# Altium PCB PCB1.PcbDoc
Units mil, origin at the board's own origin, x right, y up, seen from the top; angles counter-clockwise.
Board outline 2756 x 2756 mil, 4 copper layers (Top Layer, Internal Plane 1, Internal Plane 2, Bottom Layer), stack 18.2 mil thick; 17 components, 15 nets, 62 pads, 0 vias.
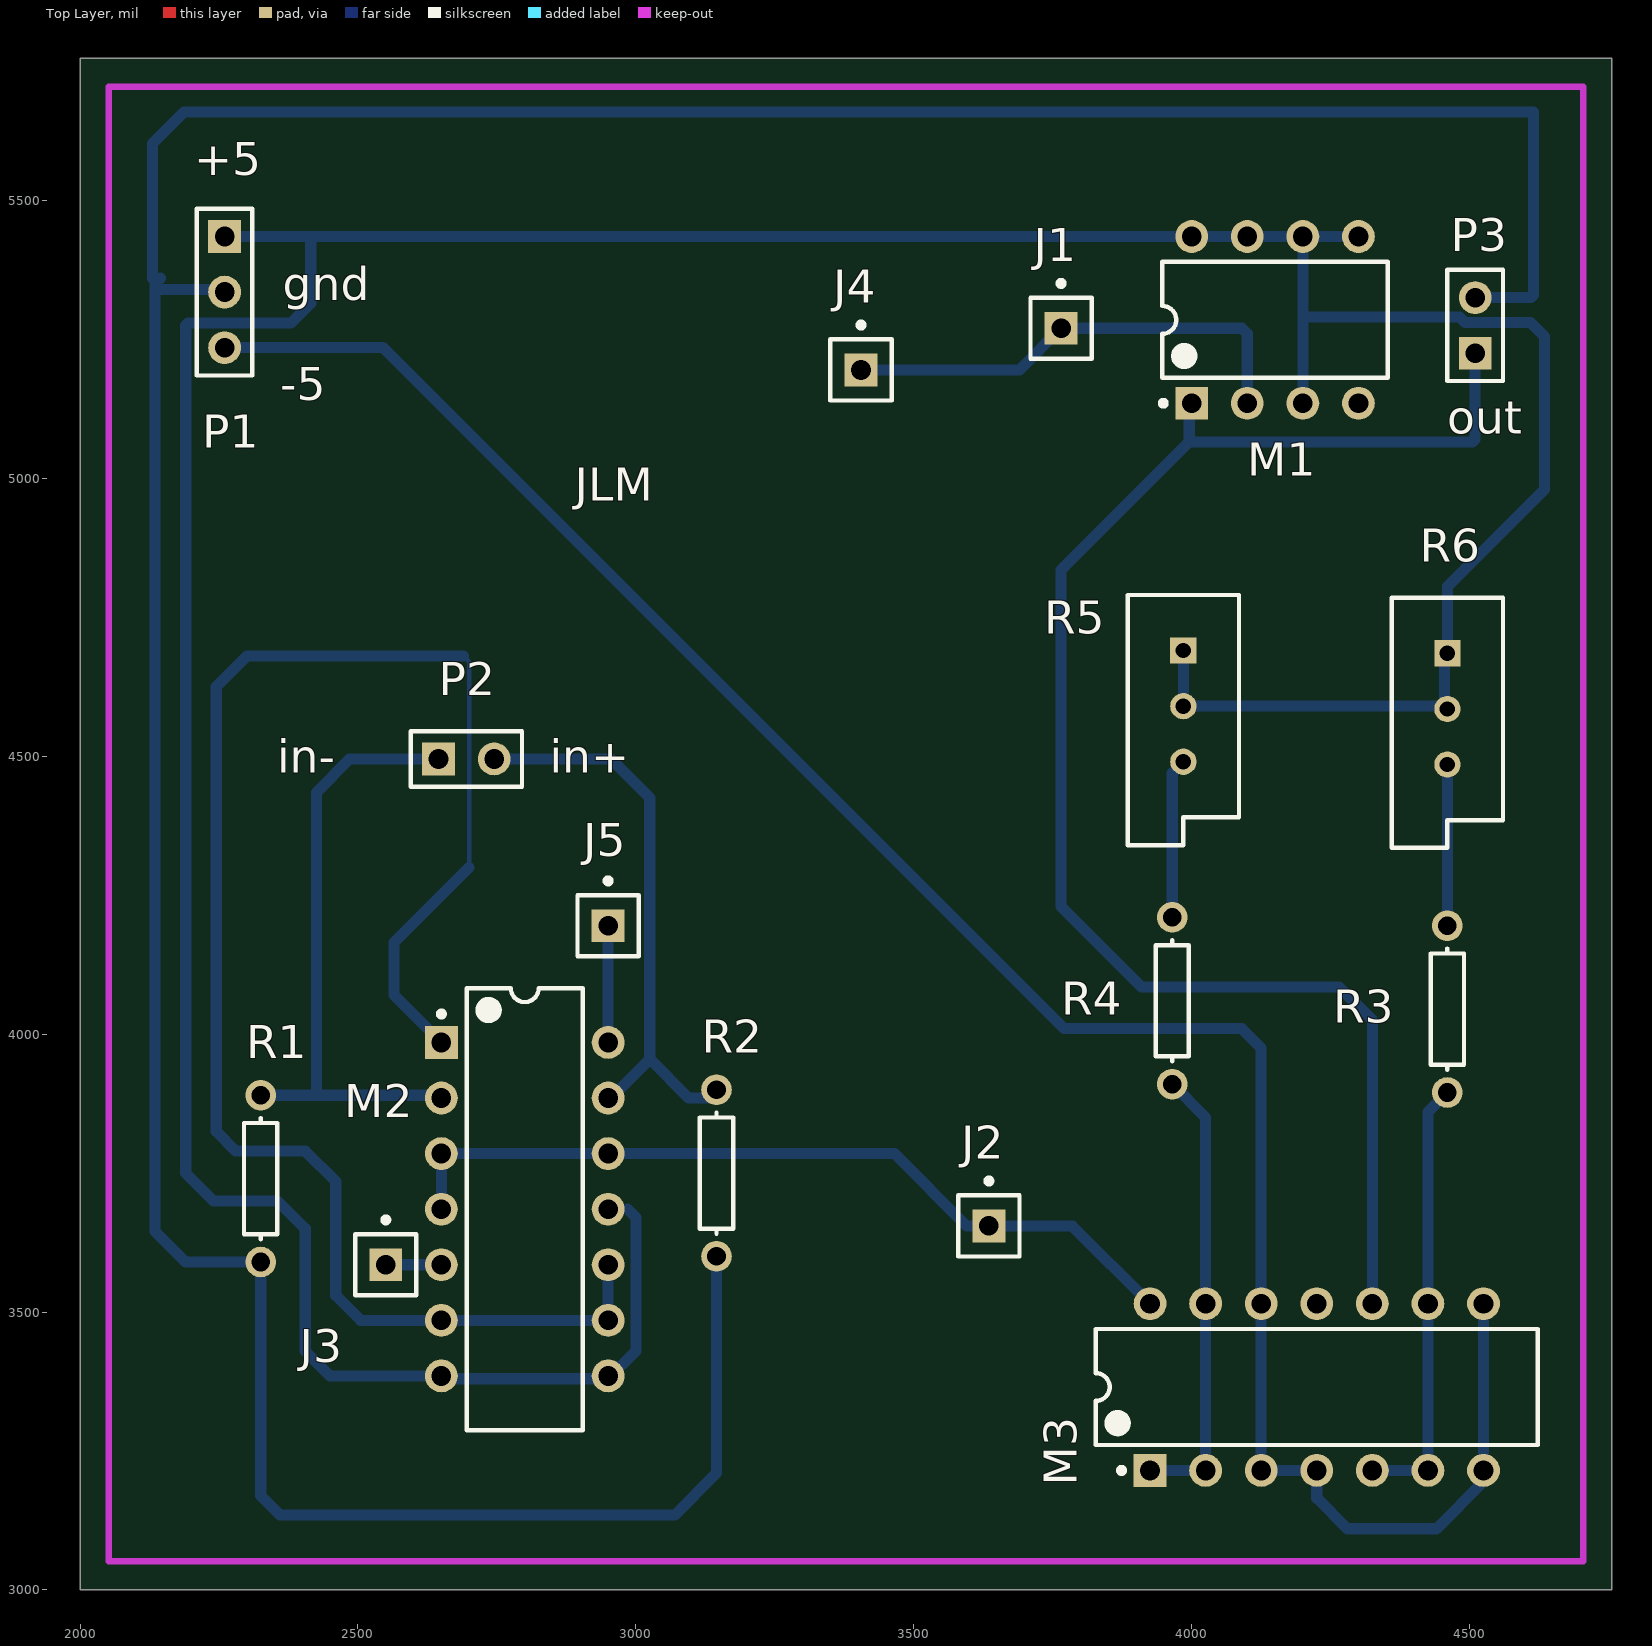
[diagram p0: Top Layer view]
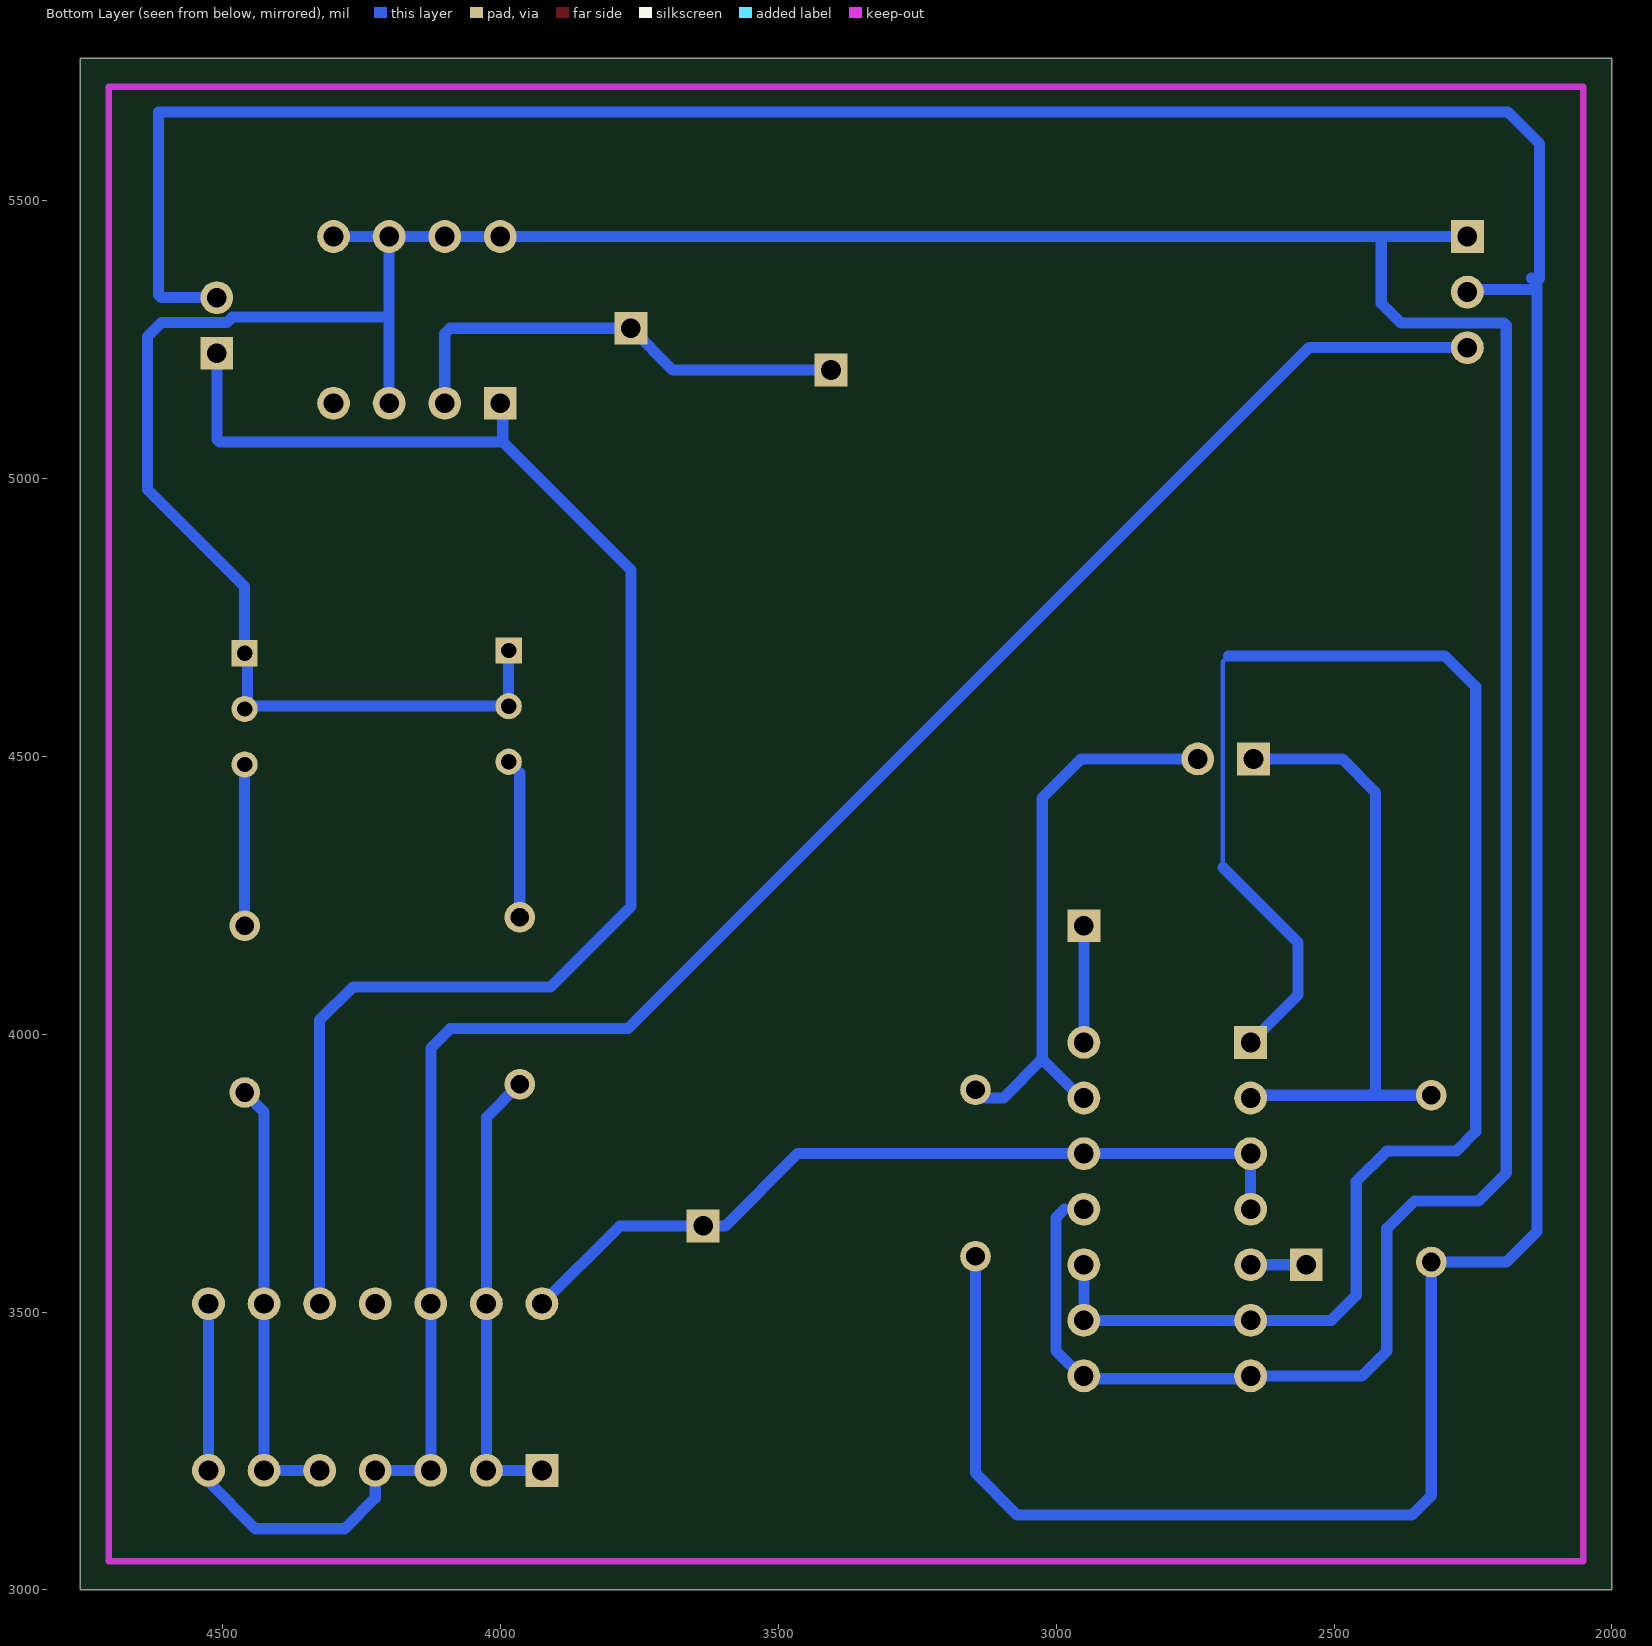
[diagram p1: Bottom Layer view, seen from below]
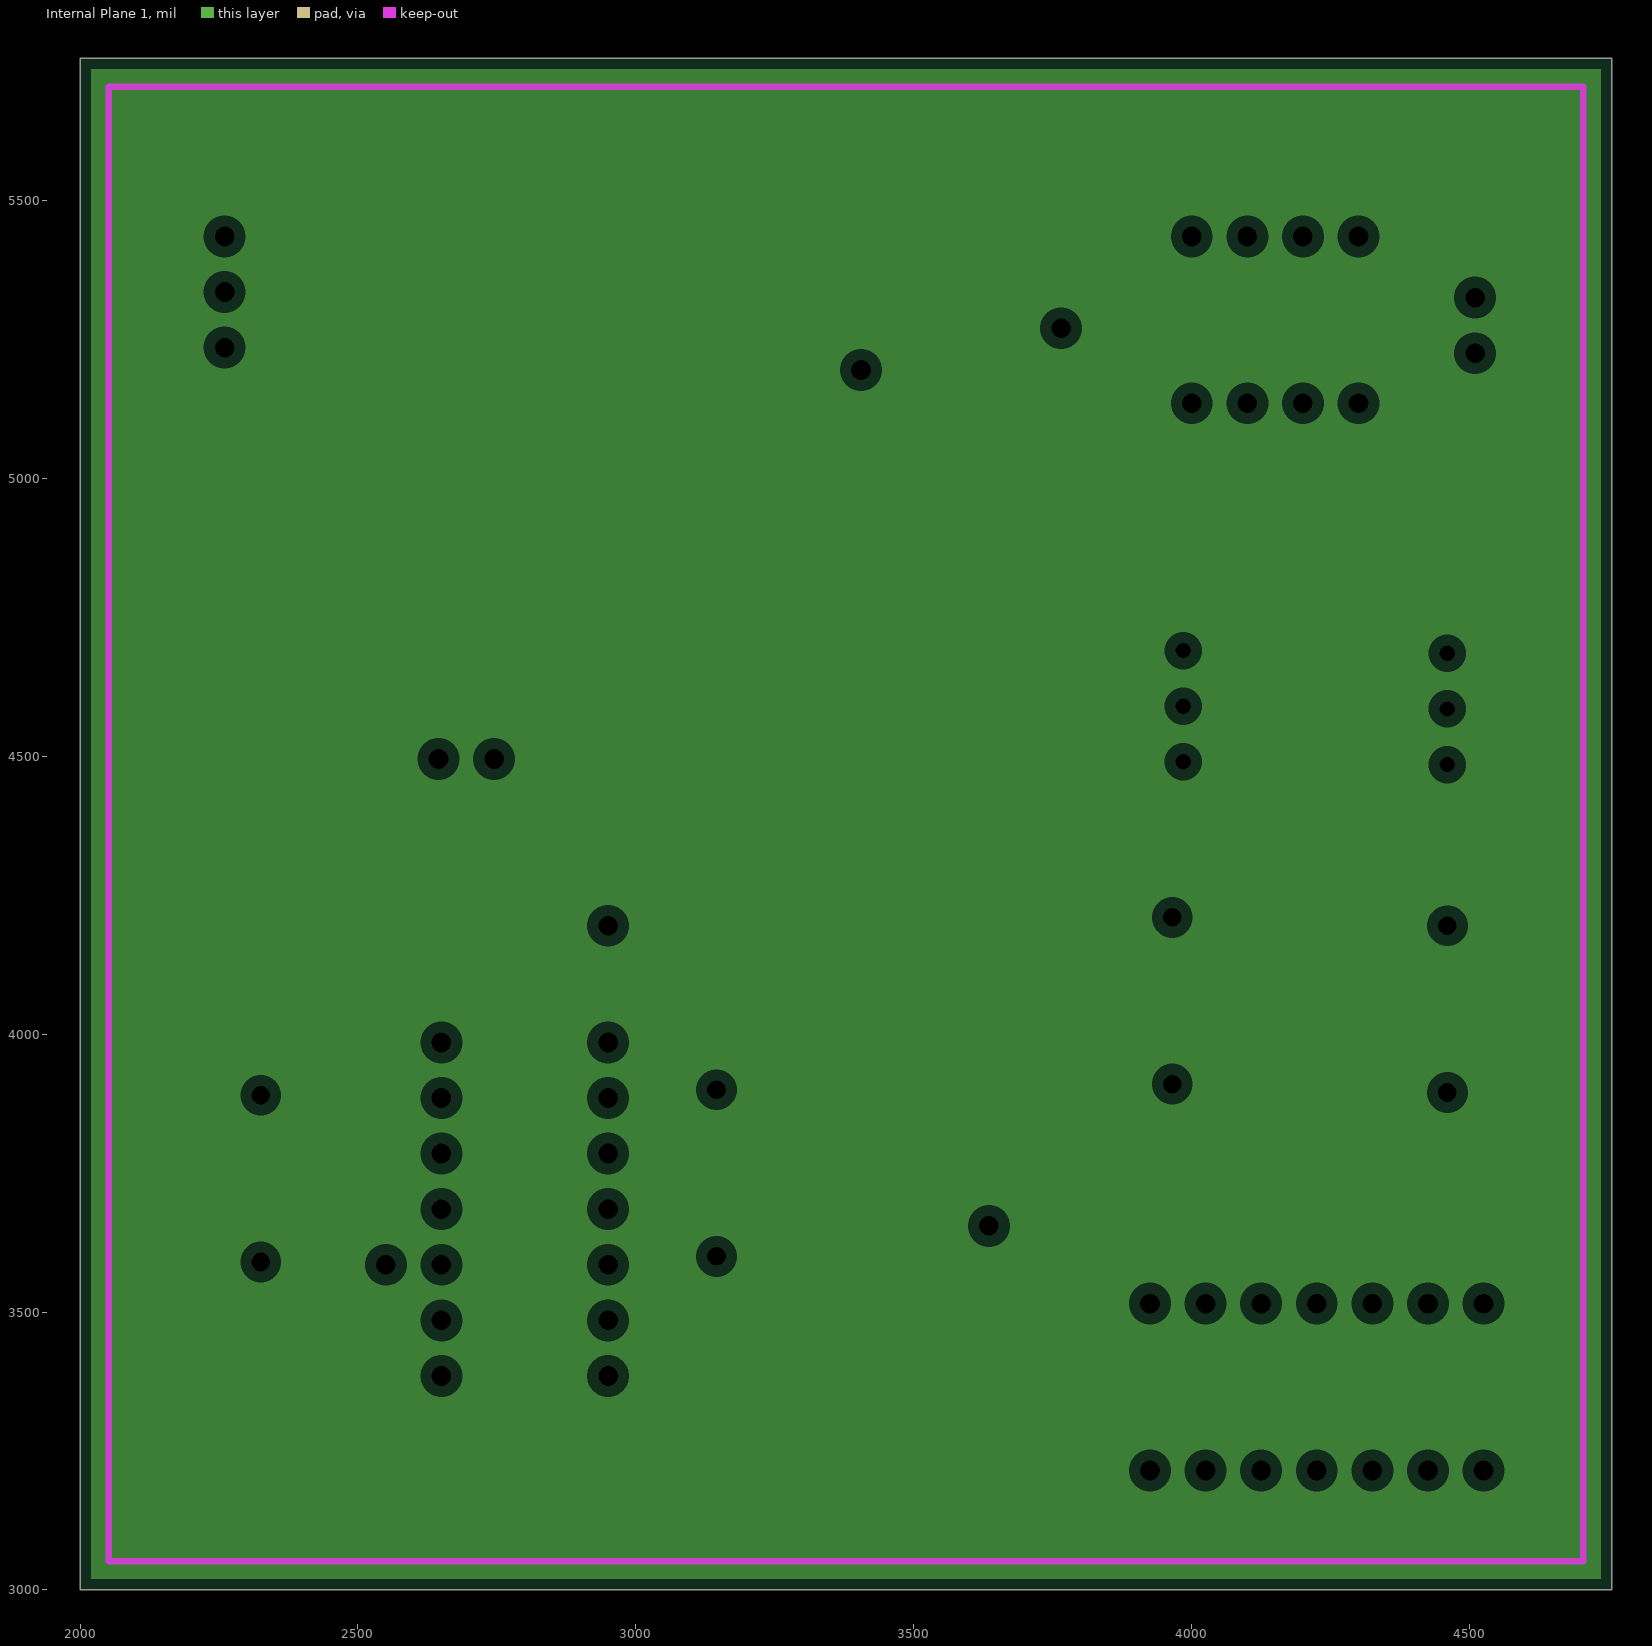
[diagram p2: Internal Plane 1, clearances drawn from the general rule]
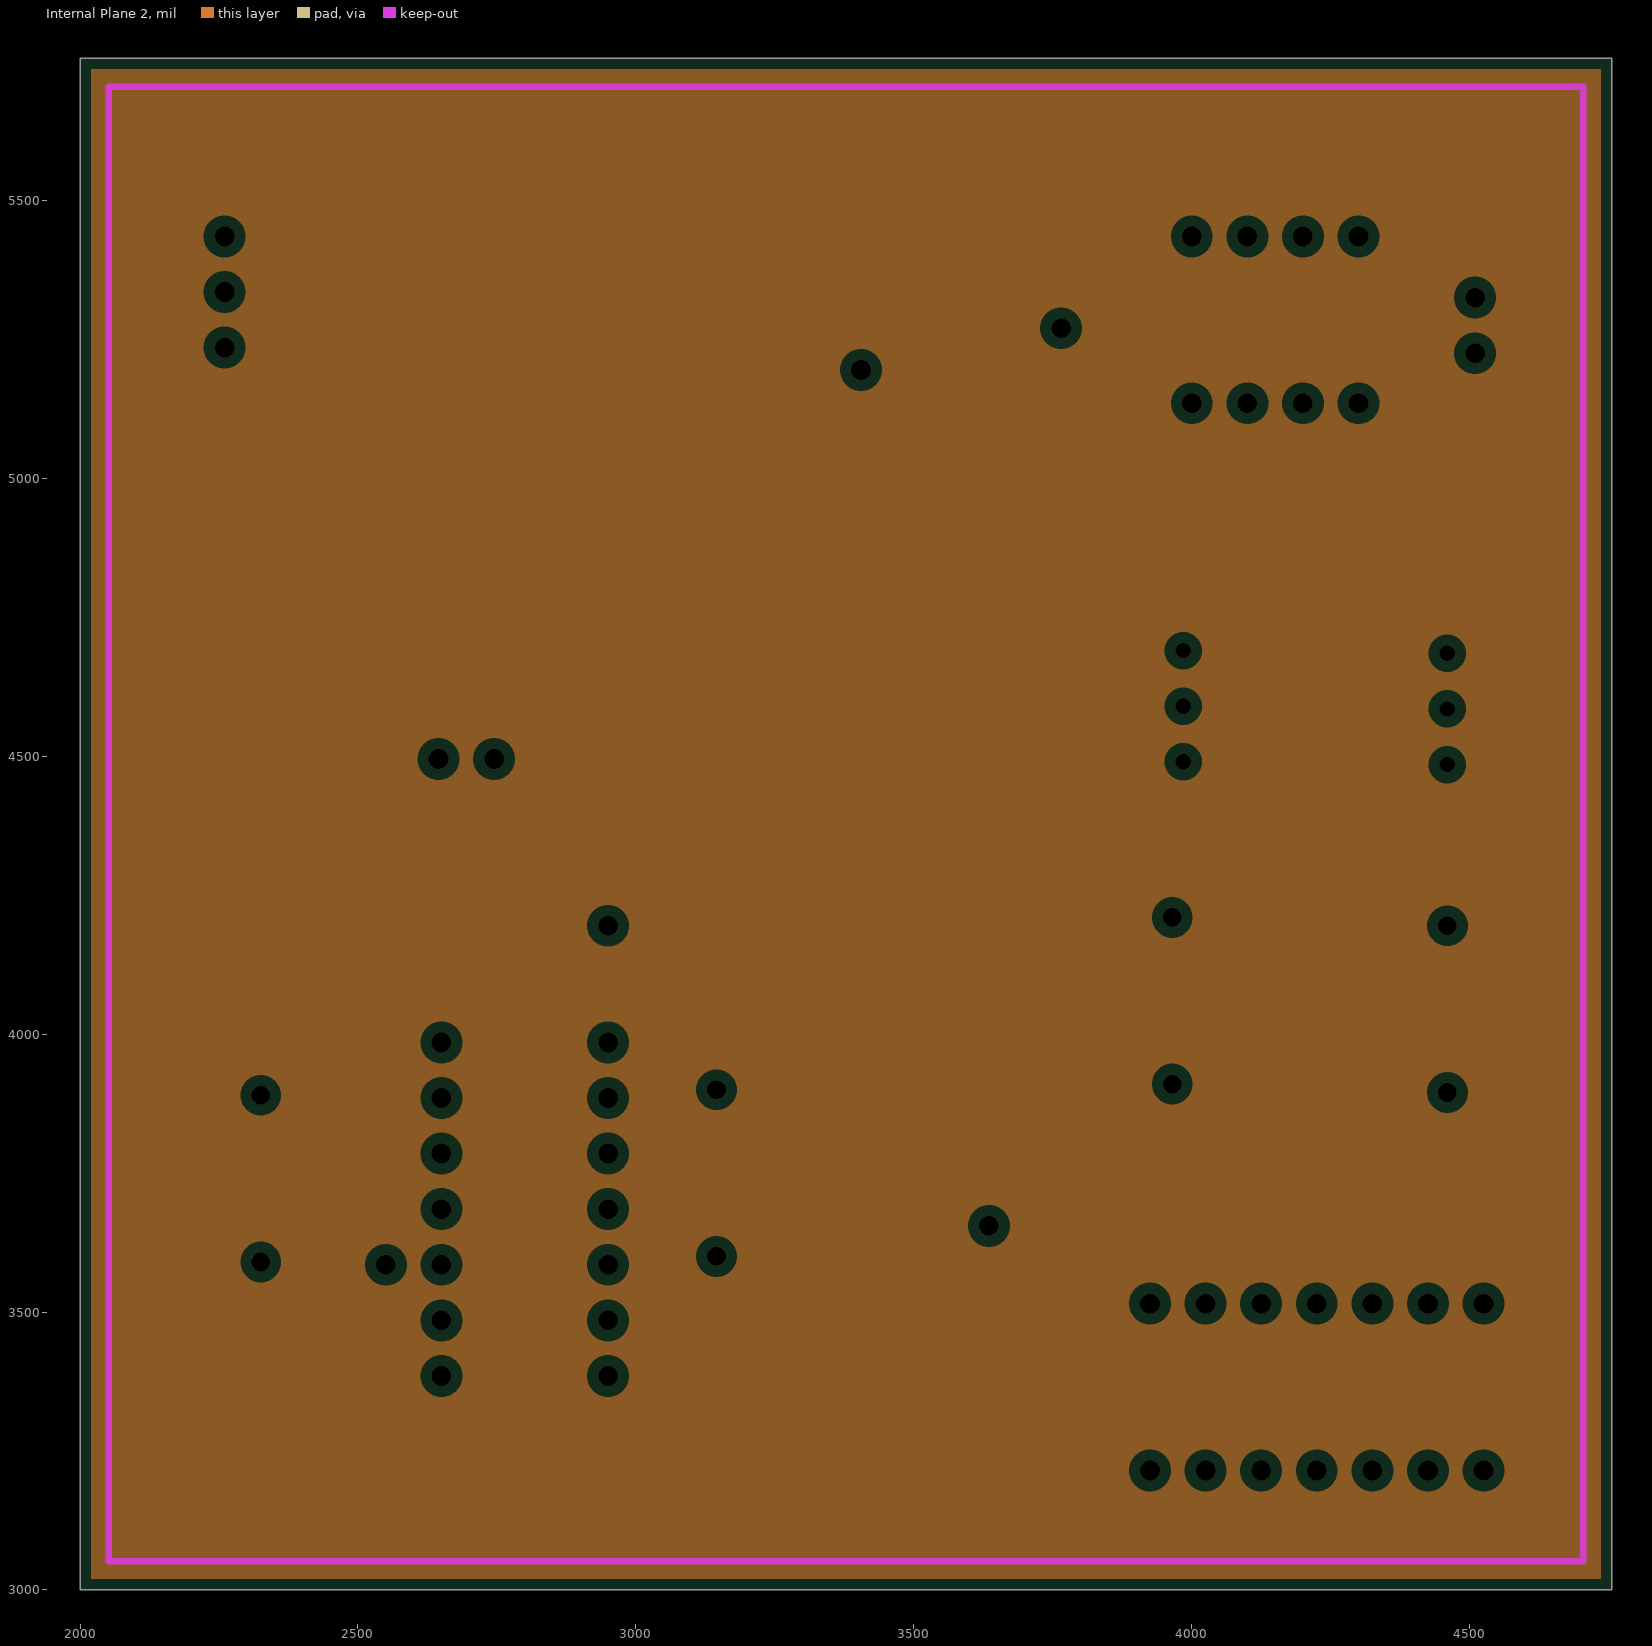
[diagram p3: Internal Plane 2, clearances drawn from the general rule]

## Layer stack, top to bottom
Top Solder: solder mask 0.4, Solder Resist, Dk 3.5
Top Layer: signal copper 1.4
Internal Plane 1: plane copper 1.4
Internal Plane 2: plane copper 1.4
Dielectric 1: dielectric 12.6, FR-4, Dk 4.8
Bottom Layer: signal copper 1.4
Bottom Solder: solder mask 0.4, Solder Resist, Dk 3.5

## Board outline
2000,3000 4756,3000 4756,5756 2000,5756

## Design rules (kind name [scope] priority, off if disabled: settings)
Clearance Clearance_2 [InNet('NetM2_1')] p1: gap=10
Clearance Clearance_1 [InNet('+5')] p2: gap=5
Clearance [All] p3: gap=30
PlaneClearance [All] p1: clearance=20
PlaneConnect [All] p1: planeconnectstyle=Relief reliefexpansion=20 reliefentries=4 reliefconductorwidth=10 reliefairgap=10
PolygonConnect [All] p1: connectstyle=Relief reliefconductorwidth=10 reliefentries=4 polygonreliefangle="90 Angle" airgapwidth=10
RoutingVias [All] p1: holewidth=32 width=62 viastyle="Through Hole" minholewidth=28 minwidth=50 maxholewidth=28 maxwidth=50
SolderMaskExpansion [All] p1: expansion=4
Width Width_1 [InNet('NetJ1_1')] p1: maxlimit=20 minlimit=5 preferedwidth=10 toplayer_minwidth=8 toplayer_maxwidth=10 minimp=50.000000 maximp=50.000000 favimp=50.000000
Width [All] p2: maxlimit=20 minlimit=8 preferedwidth=20 toplayer_minwidth=20 minimp=50.000000 maximp=50.000000 favimp=50.000000
28 further rules are at their usual default settings.

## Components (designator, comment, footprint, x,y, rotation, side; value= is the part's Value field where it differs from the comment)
J1 "Socket" PIN1 3765,5270 r0 top
J2 "Socket" PIN1 3635,3655 r0 top
J3 "Socket" PIN1 2550,3585 r0 top (schematic designator J?)
J4 "Socket" PIN1 3405,5195 r0 top (schematic designator J?)
J5 "Socket" PIN1 2950,4195 r0 top
M1 "ALD1117" DIP-8 4150,5285 r90 top
M2 "ALD1105" DIP-14 2800,3685 r0 top
M3 "ALD1106" DIP-14 4225,3365 r90 top
P1 "Header 3" HDR1X3 2260,5435 r270 top
P2 "Header 2" HDR1X2 2645,4495 r0 top (schematic designator P4)
P3 "Header 2" HDR1X2 4510,5225 r90 top (schematic designator P2)
R1 "Res1" AXIAL-0.3 2325,3740 r90 top
R2 "Res1" AXIAL-0.3 3145,3750 r90 top
R3 "RPot" VR5 4460,4585 r270 top
R4 "RPot" VR5 3985,4590 r270 top
R5 "Res1" AXIAL-0.3 3965,4060 r90 top
R6 "Res1" AXIAL-0.3 4460,4045 r90 top

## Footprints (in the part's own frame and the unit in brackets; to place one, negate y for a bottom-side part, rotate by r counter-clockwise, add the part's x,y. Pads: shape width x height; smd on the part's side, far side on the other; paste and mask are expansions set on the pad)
AXIAL-0.3 [mm] "Axial Device, Thru-Hole; 2 Leads; 0.3 in Pin Spacing"
  round 1.4 hole 0.85: 1(-3.81,0) 2(3.81,0)
  silkscreen extent -2.77,-0.76 2.77,0.76
DIP-8 [mm] "DIP, 8-Pin, Row Spacing 7.62 mm, Pitch 2.54 mm"
  rect 1.5x1.5 hole 0.9: 1(-3.81,3.81)
  round 1.5 hole 0.9: 2(-3.81,1.27) 3(-3.81,-1.27) 4(-3.81,-3.81) 5(3.81,-3.81) 6(3.81,-1.27) 7(3.81,1.27) 8(3.81,3.81)
  silkscreen extent -3.93,-5.15 2.65,5.23, body extent -3.6,-5.15 3.6,5.15, height 5.33
DIP-14 [mm] "DIP, 14-Pin, Row Spacing 7.62 mm, Pitch 2.54 mm"
  rect 1.5x1.5 hole 0.9: 1(-3.81,7.62)
  round 1.5 hole 0.9: 2(-3.81,5.08) 3(-3.81,2.54) 4(-3.81,0) 5(-3.81,-2.54) 6(-3.81,-5.08) 7(-3.81,-7.62) 8(3.81,-7.62) 9(3.81,-5.08) 10(3.81,-2.54) 11(3.81,0) 12(3.81,2.54) 13(3.81,5.08) 14(3.81,7.62)
  silkscreen extent -3.93,-10.1 2.65,10.1, body extent -3.6,-10.1 3.6,10.1, height 5.08
HDR1X2 [mm] "Connector; Header; 2 Position"
  rect 1.5x1.5 hole 0.9: 1(0,0)
  round 1.5 hole 0.9: 2(2.54,0)
  silkscreen extent -1.27,-1.27 3.81,1.27
HDR1X3 [mm] "Connector; Header; 3 Position"
  rect 1.5x1.5 hole 0.9: 1(0,0)
  round 1.5 hole 0.9: 2(2.54,0) 3(5.08,0)
  silkscreen extent -1.27,-1.27 6.35,1.27
PIN1 [mm] "Connector; Plug"
  rect 1.5x1.5 hole 0.9: 1(0,0)
  silkscreen extent -1.4,-1.4 1.4,2.17
VR5 [mm] "Thru-Hole; 3 Leads"
  rect 1.2x1.2 hole 0.7: 1(-2.54,0)
  round 1.2 hole 0.7: 2(0,0) 3(2.54,0)
  silkscreen extent -5.08,-2.54 6.35,2.54

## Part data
M1: "Dual P-channel matched MOSFET array"
M2: "Dual P-channel and dual N-channel matched MOSFET array"
M3: "Quad N-channel matched MOSFET array"
P1: "Header, 3-Pin"
P2 P3: "Header, 2-Pin"
R1 R2 R5 R6: "Resistor"
R3 R4: "Potentiometer"

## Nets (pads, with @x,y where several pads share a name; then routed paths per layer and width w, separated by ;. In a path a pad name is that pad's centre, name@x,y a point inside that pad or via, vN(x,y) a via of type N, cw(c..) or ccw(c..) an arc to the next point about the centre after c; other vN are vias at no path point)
+5: M1.3 M1.5 M1.6 M1.7 M1.8 M2.7 M2.8 M2.11 P1.1 R3.1 R3.2 R4.1 R4.2 | length 7477.6
  Bottom Layer w8: M2.11 2985,3685
  Bottom Layer w20: P1.1 2415,5435 ; 2565,3385 M2.7 2450,3385 2405,3430 2405,3650 2355,3700 2240,3700 2190,3750 2190,5275 2194.53,5279.53 2379.53,5279.53 2415,5315 2415,5435 ; M2.7@2650,3380 2950,3380 3000,3430 3000,3670 2985,3685 ; R4.1 R4.2 4455,4590 4455,4680 R3.1 4460,4805 4635,4980 4635,5255 4609.53,5280.47 4491.56,5280.47 4482.03,5290 4200,5290 ; M1.3 4200,5290 ; M1.5 M1.6 ; 2415,5435 M1.8 M1.7 M1.6 ; 4200,5290 M1.6
-5: M3.3 M3.4 M3.7 M3.8 M3.12 P1.3 | length 3974.9
  Bottom Layer w20: P1.3 2545,5235 3770,4010 4090,4010 4125,3975 M3.12 M3.3 M3.4 4225,3165 4280,3110 4440,3110 4525,3195 M3.7 M3.8
GND: P1.2 P3.2 R1.1 R2.1 | length 6911.2
  Bottom Layer w20: 2130,5360 2130,5602.09 2186.82,5658.91 4615,5658.91 4615,5330 4610,5325 P3.2 ; 2145,5360 2135,5350 2135,5340 ; P1.2 2255,5340 2135,5340 ; R1.1@2325,3580 2325,3170 2360,3135 3070,3135 3145,3210 R2.1 ; R1.1 2190,3590 2135,3645 2135,5340
NetJ1_1: J1.1 J4.1 M1.2 | length 855.2
  Bottom Layer w20: J4.1 3690,5195 J1.1 4090,5270 4100,5260 M1.2
NetJ2_1: J2.1 M2.3 M2.4 M2.12 M3.14 | length 1486.8
  Bottom Layer w20: M2.4 M2.3 3465,3785 3595,3655 J2.1 3785,3655 M3.14
NetJ3_1: J3.1 M2.5 | length 100
  Bottom Layer w20: J3.1 M2.5
NetJ5_1: J5.1 M2.14 | length 210
  Bottom Layer w20: M2.14 J5.1
NetM1_1: M1.1 M3.10 P3.1 | length 2828.7
  Bottom Layer w20: M1.1 3995.47,5130.47 3995.47,5065.47 ; M3.10 4325,4025 4265,4085 3910,4085 3765,4230 3765,4835 3995.47,5065.47 ; P3.1 4510,5070 4505.47,5065.47 3995.47,5065.47
NetM2_1: M2.1 M2.6 M2.9 M2.10 | length 3124
  Bottom Layer w8: 2690,4680 2700,4670 2700,4300
  Bottom Layer w20: M2.1 2565,4070 2565,4165 2700,4300 ; 2690,4680 2300,4680 2245,4625 2245,3825 2280,3790 2405,3790 2460,3735 2460,3530 2505,3485 M2.9 M2.10
NetM2_2: M2.2 P2.1 R1.2 | length 1121.9
  Bottom Layer w20: R1.2@2335,3890 2420,3890 ; P2.1 2485,4495 2425,4435 2425,3895 2420,3890 ; M2.2@2665,3890 2420,3890
NetM2_13: M2.13 P2.2 R2.2 | length 1038.2
  Bottom Layer w20: P2.2 2955,4495 3025,4425 3025,3955 ; M2.13 2955,3885 3025,3955 ; R2.2 3130,3885 3095,3885 3025,3955
NetM3_1: M3.1 M3.2 M3.13 R5.1 | length 819.9
  Bottom Layer w20: M3.1 M3.2 M3.13 4025,3850 R5.1
NetM3_5: M3.5 M3.6 M3.9 R6.1 | length 794.5
  Bottom Layer w20: M3.5 M3.6 M3.9 4425,3860 R6.1
NetR3_3: R3.3 R6.2 | length 290
  Bottom Layer w20: R6.2 R3.3
NetR4_3: R4.3 R5.2 | length 288.3
  Bottom Layer w20: R5.2 3965,4470 R4.3
pads on no net: M1.4 M3.11

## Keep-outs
Keep-Out Layer:
  lines w11.81: 2051.18,3051.18 2051.18,5704.82 4704.82,5704.82 4704.82,3051.18 2051.18,3051.18

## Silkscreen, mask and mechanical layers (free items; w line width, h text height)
Top Overlay:
  text "+5" at 2205,5545 h60
  text "gnd" at 2365,5320 h60
  text "-5" at 2360,5140 h60
  text "out" at 4460,5080 h60
  text "JLM" at 2890,4960 h60
  text "in-" at 2355,4470 h60
  text "in+" at 2845,4470 h60

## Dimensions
2051.18,3051.18 to 2051.18,5704.82 on Mechanical 1
2051.18,3051.18 to 4704.82,3051.18 on Mechanical 1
